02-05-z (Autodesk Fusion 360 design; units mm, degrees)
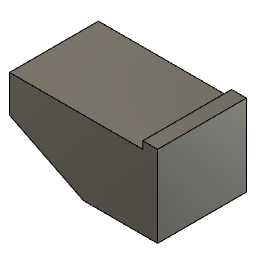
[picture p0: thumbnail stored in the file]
sketch "スケッチ1" plane through (0, 0, 0) normal (0, 0, 1) x axis (1, 0, 0)
  line L1 (-50, 25) -> (50, 25)
  line L2 (-50, -25) -> (-50, 25)
  line L3 (50, -25) -> (-50, -25)
  line L4 (50, 25) -> (50, -25)
  line L5 (-50, -25) -> (50, 25)
  line L6 (50, -25) -> (-50, 25)
  point P6 (0, 0)
  point P1 (0, 0)
  point P2 (50, 25)
  point P3 (-50, 25)
  point P5 (50, -25)
  horizontal L1
  perpendicular L1 L2
  parallel L1 L3
  parallel L2 L4
  coincident L5 P6
  coincident L6 P6
  coincident P1 P6
  dimension "d1" distance P2 P3 = 100
  dimension "d2" distance P2 P5 = 50
extrude "押し出し1" new body sketch "スケッチ1" profile of L1 L2 L3 L4 distance 60
sketch "スケッチ2" plane through (0, 25, 0) normal (0, 1, 0) x axis (-1, 0, 0)
  line L1 (50, 30) -> (50, -30)
  line L2 (-50, 30) -> (50, 30)
  line L3 (-50, -30) -> (-50, 30)
  line L4 (50, -30) -> (-50, -30)
  line L5 (-50, -30) -> (-40, -30)
  line L6 (-50, 30) -> (-50, -30)
  line L7 (-40, 30) -> (-50, 30)
  line L8 (-40, -30) -> (-40, 30)
  point P5 (-50, -30)
  point P7 (-50, -30)
  point P4 (-50, 30)
  point P8 (-50, 30)
  point P6 (-40, -30)
  horizontal L5
  vertical L6
  horizontal L7
  vertical L8
  coincident P5 P7
  coincident P4 P8
  dimension "d5" distance P6 P7 = 10
extrude "押し出し2" add sketch "スケッチ2" profile of L2 L3 L4 L5 L6 L7 L8 along normal blind 5
sketch "スケッチ4" plane through (0, 0, 30) normal (0, 0, 1) x axis (1, 0, 0)
  line L1 (50, 30) -> (50, -25)
  line L2 (40, 30) -> (50, 30)
  line L3 (40, 25) -> (40, 30)
  line L4 (-50, 25) -> (40, 25)
  line L5 (-50, -25) -> (-50, 25)
  line L6 (50, -25) -> (-50, -25)
  line L7 (0, -25) -> (-50, -25)
  line L8 (-50, 0) -> (0, -25)
  line L9 (-50, -25) -> (-50, 0)
  point P8 (-50, -25)
  point P10 (-50, 0)
  point P9 (0, -25)
  parallel L5 L9
  collinear L5 L9
  collinear L6 L7
  dimension "d10" distance P8 P10 = 25
  dimension "d11" distance P8 P9 = 50
extrude "押し出し3" cut sketch "スケッチ4" profile of L5 L6 L7 L8 L9 no distance stored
